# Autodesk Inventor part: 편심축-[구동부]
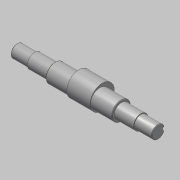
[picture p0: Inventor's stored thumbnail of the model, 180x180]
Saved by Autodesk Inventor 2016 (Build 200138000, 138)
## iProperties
Created: 2015-10
Part Number: 편심축-[구동부]
Document SubType Name: Modeling
Designer: mdu
Density: 7.86 g/cm^3
Material: 강철, 연강
Mass: 1327.93 g
Surface Area: 248.525 cm^2
Volume: 168.947 cm^3
Appearance: 강철
Author: mdu
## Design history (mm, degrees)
sketch "스케치1"
  geometry: L1 (-20.5, -41.331)-(-20.5, 32.669) reference; L2 (7.5, -30.031)-(7.5, 21.369) reference; L3 (135.5, -30.331)-(135.5, 21.669) reference; L4 (121.5, 21.369)-(121.5, -30.031) reference; L5 (184.5, -4.331)-(-57.5, -4.331); L6 (184.5, -4.331)-(184.5, 6.669); L7 (154.5, 8.169)-(121.5, 8.169); L8 (121.5, 8.169)-(121.5, 11.669); L9 (121.5, 11.669)-(7.5, 11.669); L10 (7.5, 11.669)-(7.5, 8.169); L11 (7.5, 8.169)-(-27.5, 8.169); L12 (-27.5, 8.169)-(-27.5, 6.669); L13 (-27.5, 6.669)-(-57.5, 6.669); L14 (-57.5, 6.669)-(-57.5, -4.331); L15 (154.5, 8.169)-(154.5, 6.669); L16 (154.5, 6.669)-(184.5, 6.669); C1 r 32.5 at (64.5, -4.331) reference; 1 further point
  constraints: 24 end point, 8 perpendicular, 5 point on line, 3 parallel, 2 collinear
  dimensions: "d1" = 25 diameter of L11 L5; "d2" = 32 diameter of L9 L5; "d3" = 22 diameter of L13 L5; "d4" = 35 distance of L10.end L11.end; "d5" = 30 distance of L12.end L13.end; "d15" = 33 distance of L7.start L7.end; "d26" = 30 distance of L15.end L6.end
revolve "회전1" sketch "스케치1" stored, may be unused: angle "d6" = 90 deg
node "작업 평면1"
sketch "스케치2"
  geometry: C1 r 16 at (0, 0) reference; C2 r 20.75 at (0, 4)
  constraints: 1 centre point, 1 vertical alignment
  dimensions: "d34" = 4 distance of C2.centre C1.centre; "d35" = 41.5 diameter of C2
extrude "돌출1" join sketch "스케치2" stored distance "d9" = 40; taper "d10" = 0 deg
chamfer "모따기1" distance "d11" = 1; stored, may be unused: second distance "d12" = 2, angle "d13" = 45 deg
node "작업 평면2"
sketch "스케치3"
  geometry: L1 (-15, -10)-(-15, 10) reference; L2 (-15, 3)-(0, 3); L3 (0, -3)-(-15, -3); A1 r 3 centre (0, 0) between (0, -3) and (0, 3); 2 further points
  constraints: 4 end point, 2 perpendicular, 2 point on circle, 2 point on line, 2 tangent, 1 centre point, 1 horizontal alignment, 1 midpoint
  dimensions: "d16" = 18 dimension on A1 L1; "d17" = 6 distance between parallel lines of L3 L2
extrude "돌출2" cut sketch "스케치3" distance "d18" = 3.5; taper "d19" = 0 deg
node "작업 평면3"
node "솔리드1"
mirror "대칭1"
node "참조1"
node "참조2"
node "참조3"
node "참조4"
node "참조5"
other parameters: "d30" = 35
